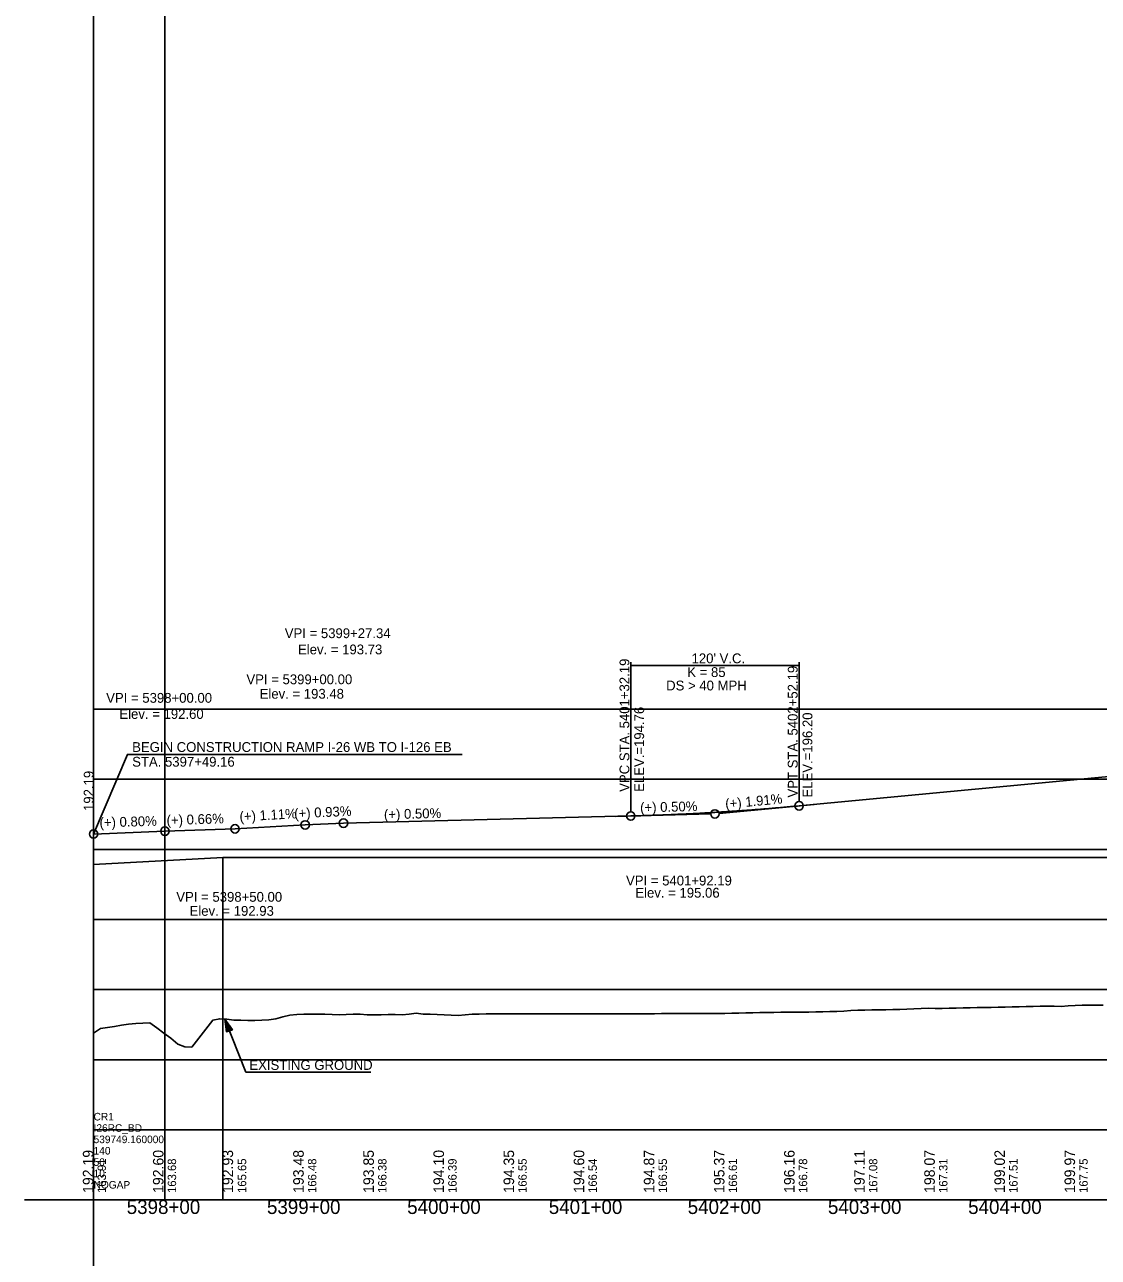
# Model space of a CAD drawing. Extents: x 69 to 2003113, y 512 to 837401.
# Drawn here: x 1883637 to 1884403, y 775948 to 776827 of the extents above; entities that cross this region are included whole.
import ezdxf

# ---------------------------------------------------------------- set-up
doc = ezdxf.new("R2010")
doc.units = 0
for name, color, linetype in [('BR_AUTO DIMENSION', 7, 'Continuous'), ('BR_BORDER LINES', 7, 'Continuous'), ('BR_CENTER LINE BASELINE', 7, 'Continuous'), ('BR_CONCRETE', 7, 'Continuous'), ('BR_GRID DOTS', 7, 'Continuous'), ('BR_GRID LINES', 7, 'Continuous'), ('BR_TEXT', 7, 'Continuous'), ('RD_HC_Points', 7, 'Continuous'), ('RD_PD_ALT1_TrvlWay', 7, 'Continuous'), ('RD_SHT_ID', 7, 'Continuous'), ('RD_SHT_IplotShp', 7, 'Continuous')]:
    doc.layers.add(name, color=color, linetype=linetype)

msp = doc.modelspace()

# ---------------------------------------------------------------- linework, layer by layer
at = {"layer": 'BR_AUTO DIMENSION'}
for p, q in [((1883686.1, 774739.14), (1883686.1, 777706.15)), ((1883736.94, 775989.14), (1883736.94, 777706.15)), ((1883686.1, 776339.14), (1888825.1, 776339.14)), ((1883686.1, 776289.14), (1888825.1, 776289.14)), ((1883686.1, 776239.14), (1888825.1, 776239.14)), ((1883686.1, 776228.39), (1883778.33, 776233.39)), ((1883778.33, 776233.39), (1883778.33, 775989.14)), ((1883778.33, 776233.39), (1884666.93, 776233.39)), ((1883686.1, 776228.39), (1883686.1, 775989.14)), ((1883686.1, 776189.14), (1888825.1, 776189.14)), ((1883686.1, 776139.14), (1888825.1, 776139.14)), ((1883686.1, 776089.14), (1888825.1, 776089.14)), ((1883686.1, 776039.14), (1888825.1, 776039.14)), ((1883636.94, 775989.14), (1888825.1, 775989.14))]:
    msp.add_line(p, q, dxfattribs=at)
at = {"layer": 'BR_BORDER LINES'}
for q in [(1883686.1, 777239.14), (1889486.1, 775989.14), (1883686.1, 774739.14)]:
    msp.add_line((1883686.1, 775989.14), q, dxfattribs=at)
at = {"layer": 'BR_CENTER LINE BASELINE'}
for p, q in [((1884199.81, 776271.17), (1884132.11, 776264.72)), ((1884058.15, 776262.66), (1884126.13, 776264.36))]:
    msp.add_line(p, q, dxfattribs=at)
for centre in [(1883836.94, 776256.54), (1883864.28, 776257.81), (1884129.13, 776264.43), (1883686.1, 776250.08), (1883736.94, 776252.12), (1883786.94, 776253.77)]:
    msp.add_circle(centre, 3, dxfattribs=at)
at = {"layer": 'BR_GRID DOTS'}
for p, q in [((1884069.13, 776372.65), (1884069.13, 776265.93)), ((1884069.13, 776370.15), (1884189.13, 776370.15)), ((1884189.13, 776372.65), (1884189.13, 776273.15))]:
    msp.add_line(p, q, dxfattribs=at)
msp.add_lwpolyline([(1883686.1, 776250.08), (1883710.21, 776306.85), (1883948.86, 776306.84)], dxfattribs=at)
for centre in [(1884189.13, 776270.15), (1884069.13, 776262.93)]:
    msp.add_circle(centre, 3, dxfattribs=at)
at = {"layer": 'BR_GRID LINES'}
for p, q in [((1884189.13, 776270.15), (1885136.94, 776360.48)), ((1883864.28, 776257.81), (1884069.13, 776262.93)), ((1883836.94, 776256.54), (1883864.28, 776257.81))]:
    msp.add_line(p, q, dxfattribs=at)
msp.add_lwpolyline([(1883686.1, 776250.08), (1883736.94, 776252.12), (1883786.94, 776253.77), (1883836.94, 776256.54)], dxfattribs=at)
msp.add_spline([(1884069.13, 776262.93), (1884071.53, 776263), (1884073.93, 776263.06), (1884076.33, 776263.13), (1884078.73, 776263.2), (1884081.13, 776263.28), (1884083.53, 776263.36), (1884085.93, 776263.44), (1884088.33, 776263.52), (1884090.73, 776263.61), (1884093.13, 776263.7), (1884095.53, 776263.8), (1884097.93, 776263.9), (1884100.33, 776264), (1884102.73, 776264.11), (1884105.13, 776264.21), (1884107.53, 776264.33), (1884109.93, 776264.44), (1884112.33, 776264.56), (1884114.73, 776264.68), (1884117.13, 776264.81), (1884119.53, 776264.94), (1884121.93, 776265.07), (1884124.33, 776265.21), (1884126.73, 776265.35), (1884129.13, 776265.49), (1884131.53, 776265.63), (1884133.93, 776265.78), (1884136.33, 776265.94), (1884138.73, 776266.09), (1884141.13, 776266.25), (1884143.53, 776266.42), (1884145.93, 776266.58), (1884148.33, 776266.75), (1884150.73, 776266.92), (1884153.13, 776267.1), (1884155.53, 776267.28), (1884157.93, 776267.46), (1884160.33, 776267.65), (1884162.73, 776267.84), (1884165.13, 776268.03), (1884167.53, 776268.23), (1884169.93, 776268.43), (1884172.33, 776268.63), (1884174.73, 776268.84), (1884177.13, 776269.05), (1884179.53, 776269.26), (1884181.93, 776269.48), (1884184.33, 776269.7), (1884186.73, 776269.93), (1884189.13, 776270.15)], degree=3, dxfattribs=at)
at = {"layer": 'BR_TEXT'}
for points in [[(1884186.1, 776123.06), (1884191.1, 776123.08), (1884196.1, 776123.16), (1884201.1, 776123.25), (1884206.1, 776123.34), (1884211.1, 776123.43), (1884216.1, 776123.54), (1884221.1, 776123.87), (1884226.1, 776124.16), (1884231.1, 776124.46), (1884236.1, 776124.55), (1884241.1, 776124.61), (1884246.1, 776124.67), (1884251.1, 776124.73), (1884256.1, 776124.83), (1884261.1, 776125.04), (1884266.1, 776125.25), (1884271.1, 776125.45), (1884276.1, 776125.66), (1884281.1, 776125.82), (1884286.1, 776125.69), (1884291.1, 776125.77), (1884296.1, 776125.86), (1884301.1, 776125.94), (1884306.1, 776126.02), (1884311.1, 776126.17), (1884316.1, 776126.33), (1884321.1, 776126.4), (1884326.1, 776126.47), (1884331.1, 776126.54), (1884336.1, 776126.65), (1884341.1, 776126.8), (1884346.1, 776126.96), (1884351.1, 776127.07), (1884356.1, 776127.19), (1884361.1, 776127.3), (1884366.1, 776127.27), (1884371.1, 776127.22), (1884376.1, 776127.19), (1884381.1, 776127.52), (1884386.1, 776127.85), (1884391.1, 776128.14), (1884396.1, 776128.13), (1884401.1, 776128.11), (1884406.1, 776128.11)], [(1883686.1, 776108.17), (1883691.1, 776111.43), (1883696.1, 776112.23), (1883701.1, 776112.87), (1883706.1, 776113.88), (1883711.1, 776114.46), (1883716.1, 776114.92), (1883721.1, 776115.21), (1883726.1, 776115.51), (1883731.1, 776111.91), (1883736.1, 776108.17), (1883741.1, 776104.5), (1883746.1, 776100.34), (1883751.1, 776098.24), (1883756.1, 776097.97), (1883761.1, 776104.44), (1883766.1, 776110.81), (1883771.1, 776117.3), (1883776.1, 776118.38), (1883781.1, 776118.01), (1883786.1, 776117.4), (1883791.1, 776117.29), (1883796.1, 776117.2), (1883801.1, 776117), (1883806.1, 776117.3), (1883811.1, 776117.6), (1883816.1, 776118.27), (1883821.1, 776119.68), (1883826.1, 776120.83), (1883831.1, 776121.36), (1883836.1, 776121.55), (1883841.1, 776121.61), (1883846.1, 776121.67), (1883851.1, 776121.72), (1883856.1, 776121.48), (1883861.1, 776121.22), (1883866.1, 776121.47), (1883871.1, 776121.7), (1883876.1, 776121.6), (1883881.1, 776121.23), (1883886.1, 776121.05), (1883891.1, 776121.11), (1883896.1, 776121.32), (1883901.1, 776121.32), (1883906.1, 776121.15), (1883911.1, 776121.52), (1883916.1, 776122.23), (1883921.1, 776121.7), (1883926.1, 776121.62), (1883931.1, 776121.48), (1883936.1, 776121.14), (1883941.1, 776120.85), (1883946.1, 776120.65), (1883951.1, 776121.07), (1883956.1, 776121.55), (1883961.1, 776121.69), (1883966.1, 776121.74), (1883971.1, 776121.82), (1883976.1, 776121.91), (1883981.1, 776121.94), (1883986.1, 776121.88), (1883991.1, 776121.83), (1883996.1, 776121.83), (1884001.1, 776121.83), (1884006.1, 776121.83), (1884011.1, 776121.83), (1884016.1, 776121.83), (1884021.1, 776121.83), (1884026.1, 776121.83), (1884031.1, 776121.83), (1884036.1, 776121.83), (1884041.1, 776121.83), (1884046.1, 776121.83), (1884051.1, 776121.83), (1884056.1, 776121.83), (1884061.1, 776121.83), (1884066.1, 776121.83), (1884071.1, 776121.83), (1884076.1, 776121.83), (1884081.1, 776121.83), (1884086.1, 776121.87), (1884091.1, 776122.05), (1884096.1, 776122.12), (1884101.1, 776122.11), (1884106.1, 776122.09), (1884111.1, 776122.07), (1884116.1, 776122.06), (1884121.1, 776122.04), (1884126.1, 776122.02), (1884131.1, 776122.09), (1884136.1, 776122.19), (1884141.1, 776122.29), (1884146.1, 776122.4), (1884151.1, 776122.5), (1884156.1, 776122.61), (1884161.1, 776122.74), (1884166.1, 776122.81), (1884171.1, 776122.88), (1884176.1, 776122.95), (1884181.1, 776123.02), (1884186.1, 776123.06)]]:
    msp.add_lwpolyline(points, dxfattribs=at)
at = {"layer": 'RD_PD_ALT1_TrvlWay'}
for p, q in [((1883779.75, 776118.11), (1883794.72, 776080.15)), ((1883783.06, 776109.73), (1883779.75, 776118.11)), ((1883779.75, 776118.11), (1883785.15, 776110.56)), ((1883779.75, 776118.11), (1883780.96, 776108.91)), ((1883780.96, 776108.91), (1883785.15, 776110.56)), ((1883794.72, 776080.15), (1883883.9, 776080.15))]:
    msp.add_line(p, q, dxfattribs=at)
for points in [[(1883782.95, 776109.81), (1883779.88, 776117.61), (1883782.92, 776109.74), (1883779.95, 776117.22), (1883782.82, 776109.74), (1883779.98, 776116.95), (1883782.71, 776109.72), (1883780.01, 776116.62), (1883782.63, 776109.67), (1883780.08, 776116.13), (1883782.52, 776109.6), (1883780.17, 776115.6), (1883782.4, 776109.6), (1883780.23, 776115.2), (1883782.32, 776109.54), (1883780.29, 776114.75), (1883782.21, 776109.56), (1883780.34, 776114.35), (1883782.15, 776109.46), (1883780.38, 776114), (1883782.02, 776109.45), (1883780.44, 776113.51), (1883781.92, 776109.39), (1883780.55, 776112.91), (1883781.82, 776109.33), (1883780.56, 776112.49), (1883781.72, 776109.29), (1883780.64, 776111.87), (1883781.6, 776109.28), (1883780.74, 776111.36), (1883781.5, 776109.18), (1883780.79, 776110.92), (1883781.4, 776109.18), (1883780.83, 776110.52), (1883781.32, 776109.09), (1883780.91, 776110.03), (1883781.2, 776109.12), (1883780.98, 776109.48), (1883781.09, 776109.12)], [(1883780.03, 776117.59), (1883783.07, 776109.86), (1883780.19, 776117.33), (1883783.18, 776109.9), (1883780.34, 776117.09), (1883783.26, 776109.9), (1883780.53, 776116.88), (1883783.32, 776109.94), (1883780.73, 776116.62), (1883783.42, 776109.96), (1883780.91, 776116.37), (1883783.49, 776109.98), (1883781.12, 776116.08), (1883783.58, 776110), (1883781.37, 776115.71), (1883783.69, 776110.07), (1883781.57, 776115.4), (1883783.78, 776110.06), (1883781.8, 776115.07), (1883783.86, 776110.11), (1883782.04, 776114.76), (1883783.94, 776110.15), (1883782.28, 776114.41), (1883783.99, 776110.22), (1883782.6, 776113.96), (1883784.09, 776110.22), (1883782.83, 776113.67), (1883784.18, 776110.22), (1883783.13, 776113.29), (1883784.25, 776110.29), (1883783.37, 776112.88), (1883784.35, 776110.34), (1883783.59, 776112.57), (1883784.43, 776110.44), (1883783.84, 776112.29), (1883784.5, 776110.46), (1883784.13, 776111.82), (1883784.65, 776110.44), (1883784.31, 776111.55), (1883784.79, 776110.5), (1883784.5, 776111.38), (1883784.89, 776110.64), (1883785.01, 776110.59), (1883784.86, 776110.62)]]:
    msp.add_lwpolyline(points, dxfattribs=at)

# ---------------------------------------------------------------- texts
at = {"layer": 'BR_BORDER LINES'}
for s, p in [('CR1', (1883686.1, 776045.84)), ('I26RC_BD', (1883686.1, 776037.74)), ('539749.160000', (1883686.1, 776029.64)), ('140', (1883686.1, 776021.54)), ('50', (1883686.1, 776013.44)), ('10', (1883686.1, 776005.34)), ('NOGAP', (1883686.1, 775997.24))]:
    msp.add_text(s, height=5.4, dxfattribs=at).set_placement(p)
at = {"layer": 'BR_CENTER LINE BASELINE'}
for s, rotation, p in [('(+) 1.91%', 5.44397, (1884136.84, 776268.05)), ('(+) 0.93%', 2.67005, (1883829.3, 776261.19)), ('(+) 0.50%', 1.43209, (1883893.22, 776260.54)), ('(+) 0.50%', 1.43209, (1884075.88, 776265.44)), ('(+) 0.80%', 1.75005, (1883690.41, 776254.74)), ('(+) 0.66%', 1.88435, (1883738.24, 776256.38)), ('(+) 1.11%', 3.17094, (1883790.34, 776259.03))]:
    msp.add_text(s, height=7, rotation=rotation, dxfattribs=at).set_placement(p)
at = {"layer": 'BR_CONCRETE'}
for s, height, p in [('VPC STA. 5401+32.19 ', 7, (1884068.13, 776280.15)), ('VPT STA. 5402+52.19 ', 7, (1884188.13, 776276.09)), ('ELEV.=194.76', 7, (1884078.63, 776280.15)), ('ELEV.=196.20', 7, (1884198.63, 776276.09)), ('163.91', 6, (1883694.94, 775994.14)), ('163.68', 6, (1883744.94, 775994.14)), ('165.65', 6, (1883794.94, 775994.14)), ('166.48', 6, (1883844.94, 775994.14)), ('166.38', 6, (1883894.94, 775994.14)), ('166.39', 6, (1883944.94, 775994.14)), ('166.55', 6, (1883994.94, 775994.14)), ('166.54', 6, (1884044.94, 775994.14)), ('166.55', 6, (1884094.94, 775994.14)), ('166.61', 6, (1884144.94, 775994.14)), ('166.78', 6, (1884194.94, 775994.14)), ('167.08', 6, (1884244.94, 775994.14)), ('167.31', 6, (1884294.94, 775994.14)), ('167.51', 6, (1884344.94, 775994.14)), ('167.75', 6, (1884394.94, 775994.14))]:
    msp.add_text(s, height=height, rotation=90, dxfattribs=at).set_placement(p)
at = {"layer": 'BR_GRID DOTS'}
for s, p in [("120' V.C.", (1884112.48, 776371.83)), ('K = 85', (1884109.44, 776362.02)), ('DS > 40 MPH', (1884094.35, 776352.46))]:
    msp.add_text(s, height=7, dxfattribs=at).set_placement(p)
at = {"layer": 'RD_HC_Points'}
for s, p in [('192.19', (1883685.94, 775994.14)), ('192.60', (1883735.94, 775994.14)), ('192.93', (1883785.55, 775994.14)), ('193.48', (1883835.94, 775994.14)), ('193.85', (1883885.94, 775994.14)), ('194.10', (1883935.94, 775994.14)), ('194.35', (1883985.94, 775994.14)), ('194.60', (1884035.94, 775994.14)), ('194.87', (1884085.94, 775994.14)), ('195.37', (1884135.94, 775994.14)), ('196.16', (1884185.94, 775994.14)), ('197.11', (1884235.94, 775994.14)), ('198.07', (1884285.94, 775994.14)), ('199.02', (1884335.94, 775994.14)), ('199.97', (1884385.94, 775994.14))]:
    msp.add_text(s, height=7.5, rotation=90, dxfattribs=at).set_placement(p)
at = {"layer": 'RD_PD_ALT1_TrvlWay'}
msp.add_text('EXISTING GROUND', height=7, dxfattribs=at).set_placement((1883797.18, 776081.88))
at = {"layer": 'RD_SHT_ID'}
for s, p in [('5398+00', (1883709.72, 775979.14)), ('5399+00', (1883809.72, 775979.14)), ('5400+00', (1883909.72, 775979.14)), ('5401+00', (1884010.68, 775979.14)), ('5402+00', (1884109.72, 775979.14)), ('5403+00', (1884209.72, 775979.14)), ('5404+00', (1884309.72, 775979.14))]:
    msp.add_text(s, height=10, dxfattribs=at).set_placement(p)
at = {"layer": 'RD_SHT_IplotShp'}
for s, p in [('VPI = 5399+27.34', (1883822.42, 776389.76)), ('Elev. = 193.73', (1883831.87, 776378.18)), ('VPI = 5399+00.00', (1883795.08, 776356.88)), ('VPI = 5398+00.00', (1883695.08, 776343.66)), ('Elev. = 193.48', (1883804.51, 776346.56)), ('Elev. = 192.60', (1883704.49, 776332.16)), ('BEGIN CONSTRUCTION RAMP I-26 WB TO I-126 EB', (1883713.61, 776308.59)), ('STA. 5397+49.16', (1883713.61, 776298.09)), ('VPI = 5401+92.19', (1884065.76, 776213.4)), ('VPI = 5398+50.00', (1883745.08, 776201.77)), ('Elev. = 195.06', (1884072.41, 776204.69)), ('Elev. = 192.93', (1883754.53, 776191.77))]:
    msp.add_text(s, height=7, dxfattribs=at).set_placement(p)
msp.add_text('192.19', height=7, rotation=90, dxfattribs=at).set_placement((1883686.1, 776266.5))

doc.saveas('drawing.dxf')
